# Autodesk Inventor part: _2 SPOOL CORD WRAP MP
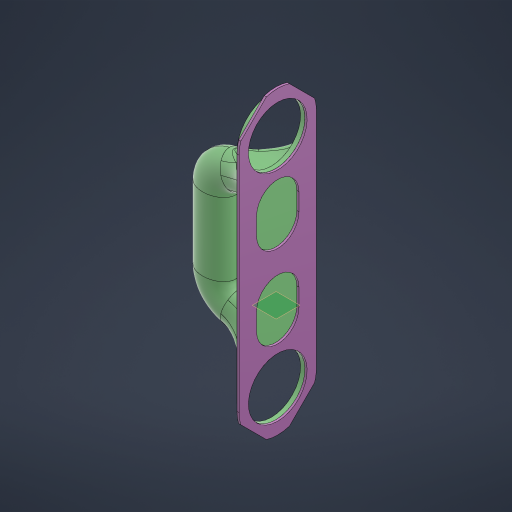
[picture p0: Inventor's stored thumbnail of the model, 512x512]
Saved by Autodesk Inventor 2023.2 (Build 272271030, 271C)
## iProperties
Created: 2022-11
Part Number: _2 SPOOL CORD WRAP MP
Material: Generic
Document SubType Name: Modeling
Designer: AR
Mass: 1228.76 g
Surface Area: 5671.02 cm^2
Volume: 1228.76 cm^3
Density: 1 g/cm^3
Appearance: Default
Author: AR
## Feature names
1. Revolution1
2. Revolution10
3. Mirror11
4. Revolution2
5. Extrusion1
6. Extrusion2
7. Extrusion26
8. Revolution3
9. Fillet1
10. Fillet3
11. Circular Pattern3
12. Revolution4
13. Fillet2
14. Fillet4
15. Circular Pattern2
16. Extrusion3
17. Fillet5
18. Mirror3
19. Mirror10
20. Chamfer3
21. Mirror4
22. Extrusion4
23. Fillet6
24. Fillet7
25. Mirror5
26. Mirror6
27. Revolution5
28. Revolution6
29. Coil1
30. Split1
31. Split2
32. Coil2
33. Fillet8
34. Fillet9
35. Fillet10
36. Extrusion5
37. Rectangular Pattern2
38. Revolution8
39. Revolution9
40. Fillet11
41. Fillet12
42. Extrusion11
43. Extrusion12
44. Extrusion13
45. Fillet15
46. Circular Pattern4
47. Extrusion14
48. Fillet16
49. Extrusion15
50. Fillet18
51. Mirror8
52. Sweep1
53. Loft2
54. Mirror9
55. Rectangular Pattern3
56. Extrusion25
57. Extrusion27
58. Extrusion24
59. Extrusion28
60. Fillet29
61. Fillet31
62. Split3
63. Extrusion29
## Parameters: d1 = 59 mm, d2 = 51 mm, d3 = 199 mm, d4 = 87 mm, d5 = 2 mm, d8 = 4.5 mm, d9 = 2.3 mm, d10 = 90 deg, d13 = 360 deg, d14 = 2.4 mm, d15 = 7.6 mm, d17 = 0, d18 = 205 mm, d22 = 1 mm, d23 = 1.14643 mm, d24 = 0.25 mm, d25 = 6.6 mm, d26 = 6 mm, d27 = 2 mm, d28 = 0.25 mm, d29 = 1 mm, d30 = 0.25 mm, d31 = 1 mm, d32 = 45 deg, d33 = 3 mm, d34 = 0.25 mm, d35 = 0.25 mm, d36 = 1 mm, d37 = 45 deg, d38 = 1 mm, d39 = 2 mm, d40 = 1 mm, d41 = 1 mm, d43 = 2 mm, d44 = 0, d45 = 15 deg, d46 = 2 mm, d50 = 3 deg, d51 = 0.75 mm, d53 = 30 deg, d55 = 3 mm, d56 = 3 mm, d60 = 0, d61 = 0, d62 = 6 mm, d68 = 360 deg, d70 = 0.75 mm, d71 = 2 mm, d72 = 45 deg, d73 = 4 mm, d74 = 1.9 mm, d75 = 1.9 mm, d76 = 0, d77 = 2 mm, d78 = 1 mm, d79 = 15 mm, d81 = 2 mm, d82 = 46 mm, d84 = 2 mm, d85 = 38.5 mm, d86 = 8 mm, d87 = 0.2 mm, d88 = 8 mm, d90 = 2 mm, d91 = 12 mm, d92 = 5.95 mm, d94 = 2 mm, d95 = 0.1 mm, d96 = 0.2 mm, d97 = 3 mm, d98 = 90 deg, d99 = 90 deg, d100 = 21.20083 mm, d101 = 2 mm, d102 = 3 mm, d103 = 21.20083 mm, d105 = 0, d106 = 90 deg, d107 = 90 deg, d108 = 0, d109 = 0, d110 = 3 mm, d111 = 24.40166 mm, d113 = 0, d114 = 90 deg, d115 = 90 deg, d116 = 0, d117 = 0, d118 = 0.5 mm, d119 = 0.2 mm, d120 = 0.5 mm, d121 = 0.25 mm, d122 = 0.25 mm, d123 = 18.2 mm, d124 = 0, d125 = 0, d126 = 0.25 mm, d127 = 18.2 mm, d128 = 4 mm, d144 = 6 mm, d160 = 3 mm, d161 = 4.20083 mm, d163 = 18 mm, d164 = 2 mm, d166 = 2 mm, d167 = 6 mm, d168 = 12 mm, d169 = 4 mm, d170 = 0, d171 = 4 mm, d173 = 0, d175 = 0, d177 = 360 deg, d179 = 9.5 mm, d180 = 0, d181 = 6 mm, d182 = 2 mm, d184 = 2 mm, d185 = 3 mm, d186 = 0.25 mm, d187 = 3 mm, d188 = 1 mm, d189 = 1 mm, d190 = 0.25 mm, d191 = 1 mm, d192 = 45 deg, d193 = 3 mm, d194 = 10.7 mm, d195 = 8 mm, d196 = 10.50777 mm, d197 = 9 mm, d198 = 0, d199 = 2 mm, d206 = 1 mm, d228 = 1 mm, d233 = 180 deg, d236 = 180 deg, d242 = 3 mm, d243 = 4 mm, d244 = 7 mm, d245 = 16 mm, d272 = 12.5 mm, d273 = 17.5 mm, d276 = 3 mm, d279 = 6 mm, d280 = 12 mm, d281 = 12.5 mm, d282 = 4 mm, d283 = 0, d284 = 0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
